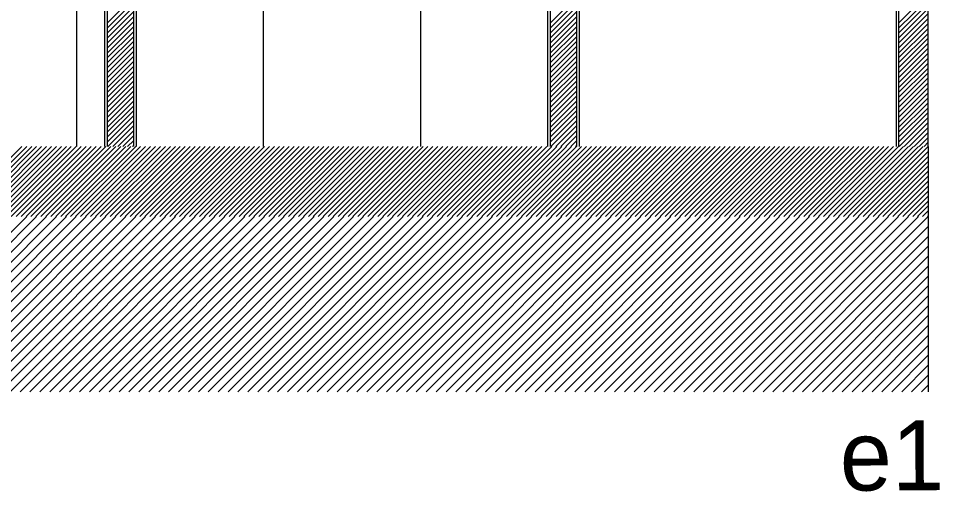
# Model space of a CAD drawing. Extents: x -4333 to -3435, y 16386 to 16556.
# Drawn here: x -3478.31 to -3473.05, y 16401.6 to 16404.3 of the extents above; entities that cross this region are included whole.
import ezdxf

# ---------------------------------------------------------------- set-up
doc = ezdxf.new("R2010")
doc.units = 0
doc.layers.add('Level 2', color=7, linetype='Continuous')
doc.layers.add('Level 63', color=7, linetype='Continuous')

msp = doc.modelspace()

# ---------------------------------------------------------------- linework, layer by layer
at = {"layer": 'Level 2'}
for p, q in [((-3473.1151, 16403.5694), (-3473.1151, 16407.0203)), ((-3477.8183, 16406.6203), (-3477.8184, 16403.5694)), ((-3477.6383, 16406.6203), (-3477.6384, 16403.5694)), ((-3475.2886, 16406.6203), (-3475.2886, 16403.5694)), ((-3475.1085, 16406.6203), (-3475.1086, 16403.5694)), ((-3473.299, 16406.6203), (-3473.299, 16403.5694)), ((-3473.1151, 16403.5694), (-3473.1151, 16402.1694))]:
    msp.add_line(p, q, dxfattribs=at)
at = {"layer": 'Level 63'}
for p, q in [((-3477.9791, 16406.6203), (-3477.9791, 16403.5694)), ((-3477.8033, 16406.6203), (-3477.8034, 16403.5694)), ((-3477.6533, 16406.6203), (-3477.6534, 16403.5694)), ((-3475.2736, 16406.6203), (-3475.2736, 16403.5694)), ((-3475.1235, 16406.6203), (-3475.1236, 16403.5694)), ((-3473.284, 16406.6203), (-3473.284, 16403.5694)), ((-3476.9134, 16405.5694), (-3476.9135, 16403.5694)), ((-3476.0135, 16405.5694), (-3476.0135, 16403.5694)), ((-3477.8034, 16404.2727), (-3477.6534, 16404.4227)), ((-3475.2736, 16404.2727), (-3475.1236, 16404.4227)), ((-3473.284, 16404.2727), (-3473.1151, 16404.4416)), ((-3473.284, 16404.2444), (-3473.1151, 16404.4133)), ((-3477.8034, 16404.2444), (-3477.6534, 16404.3944)), ((-3477.8034, 16404.2161), (-3477.6534, 16404.3661)), ((-3475.2736, 16404.2444), (-3475.1236, 16404.3944)), ((-3475.2736, 16404.2161), (-3475.1236, 16404.3661)), ((-3473.284, 16404.2161), (-3473.1151, 16404.385)), ((-3473.284, 16404.1878), (-3473.1151, 16404.3567)), ((-3477.8034, 16404.1878), (-3477.6534, 16404.3378)), ((-3477.8034, 16404.1596), (-3477.6534, 16404.3096)), ((-3475.2736, 16404.1878), (-3475.1236, 16404.3379)), ((-3475.2736, 16404.1595), (-3475.1236, 16404.3096)), ((-3473.284, 16404.1595), (-3473.1151, 16404.3284)), ((-3473.284, 16404.1313), (-3473.1151, 16404.3002)), ((-3477.8034, 16404.1313), (-3477.6534, 16404.2813)), ((-3477.8034, 16404.103), (-3477.6534, 16404.253)), ((-3475.2736, 16404.1313), (-3475.1236, 16404.2813)), ((-3475.2736, 16404.103), (-3475.1236, 16404.253)), ((-3473.284, 16404.103), (-3473.1151, 16404.2719)), ((-3477.8034, 16404.0747), (-3477.6534, 16404.2247)), ((-3477.8034, 16404.0464), (-3477.6534, 16404.1964)), ((-3475.2736, 16404.0747), (-3475.1236, 16404.2247)), ((-3475.2736, 16404.0464), (-3475.1236, 16404.1964)), ((-3473.284, 16404.0747), (-3473.1151, 16404.2436)), ((-3473.284, 16404.0464), (-3473.1151, 16404.2153)), ((-3477.8034, 16404.0181), (-3477.6534, 16404.1681)), ((-3475.2736, 16404.0181), (-3475.1236, 16404.1682)), ((-3473.284, 16404.0181), (-3473.1151, 16404.187)), ((-3473.284, 16403.9898), (-3473.1151, 16404.1587)), ((-3477.8034, 16403.9899), (-3477.6534, 16404.1399)), ((-3477.8034, 16403.9616), (-3477.6534, 16404.1116)), ((-3475.2736, 16403.9898), (-3475.1236, 16404.1399)), ((-3475.2736, 16403.9616), (-3475.1236, 16404.1116)), ((-3473.284, 16403.9615), (-3473.1151, 16404.1305)), ((-3473.284, 16403.9333), (-3473.1151, 16404.1022)), ((-3477.8034, 16403.9333), (-3477.6534, 16404.0833)), ((-3477.8034, 16403.905), (-3477.6534, 16404.055)), ((-3475.2736, 16403.9333), (-3475.1236, 16404.0833)), ((-3475.2736, 16403.905), (-3475.1236, 16404.055)), ((-3473.284, 16403.905), (-3473.1151, 16404.0739)), ((-3473.284, 16403.8767), (-3473.1151, 16404.0456)), ((-3477.8034, 16403.8767), (-3477.6534, 16404.0267)), ((-3477.8034, 16403.8484), (-3477.6534, 16403.9984)), ((-3475.2736, 16403.8767), (-3475.1236, 16404.0267)), ((-3475.2736, 16403.8484), (-3475.1236, 16403.9984)), ((-3473.284, 16403.8484), (-3473.1151, 16404.0173)), ((-3473.284, 16403.8201), (-3473.1151, 16403.989)), ((-3477.8034, 16403.8202), (-3477.6534, 16403.9701)), ((-3477.8034, 16403.7919), (-3477.6534, 16403.9419)), ((-3475.2736, 16403.8201), (-3475.1236, 16403.9702)), ((-3475.2736, 16403.7918), (-3475.1236, 16403.9419)), ((-3473.284, 16403.7918), (-3473.1151, 16403.9608)), ((-3473.284, 16403.7636), (-3473.1151, 16403.9325)), ((-3477.8034, 16403.7636), (-3477.6534, 16403.9136)), ((-3477.8034, 16403.7353), (-3477.6534, 16403.8853)), ((-3475.2736, 16403.7636), (-3475.1236, 16403.9136)), ((-3475.2736, 16403.7353), (-3475.1236, 16403.8853)), ((-3473.284, 16403.7353), (-3473.1151, 16403.9042)), ((-3477.8034, 16403.707), (-3477.6534, 16403.857)), ((-3477.8034, 16403.6787), (-3477.6534, 16403.8287)), ((-3475.2736, 16403.707), (-3475.1236, 16403.857)), ((-3475.2736, 16403.6787), (-3475.1236, 16403.8287)), ((-3473.284, 16403.707), (-3473.1151, 16403.8759)), ((-3473.284, 16403.6787), (-3473.1151, 16403.8476)), ((-3477.8034, 16403.6504), (-3477.6534, 16403.8004)), ((-3475.2736, 16403.6504), (-3475.1236, 16403.8005)), ((-3473.284, 16403.6504), (-3473.1151, 16403.8193)), ((-3473.284, 16403.6221), (-3473.1151, 16403.791)), ((-3477.8034, 16403.6222), (-3477.6534, 16403.7722)), ((-3477.8034, 16403.5939), (-3477.6534, 16403.7439)), ((-3475.2736, 16403.6221), (-3475.1236, 16403.7722)), ((-3475.2736, 16403.5939), (-3475.1236, 16403.7439)), ((-3473.284, 16403.5938), (-3473.1151, 16403.7628)), ((-3473.2802, 16403.5694), (-3473.1151, 16403.7345)), ((-3477.7995, 16403.5694), (-3477.6534, 16403.7156)), ((-3477.7713, 16403.5694), (-3477.6534, 16403.6873)), ((-3475.2698, 16403.5694), (-3475.1236, 16403.7156)), ((-3475.2415, 16403.5694), (-3475.1236, 16403.6873)), ((-3473.2519, 16403.5694), (-3473.1151, 16403.7062)), ((-3473.2236, 16403.5694), (-3473.1151, 16403.6779)), ((-3477.743, 16403.5694), (-3477.6534, 16403.659)), ((-3477.7147, 16403.5694), (-3477.6534, 16403.6307)), ((-3475.2132, 16403.5694), (-3475.1236, 16403.659)), ((-3475.1849, 16403.5694), (-3475.1236, 16403.6307)), ((-3473.1954, 16403.5694), (-3473.1151, 16403.6496)), ((-3473.1671, 16403.5694), (-3473.1151, 16403.6213)), ((-3478.691, 16403.1694), (-3478.291, 16403.5694)), ((-3478.6627, 16403.1694), (-3478.2627, 16403.5694)), ((-3478.6344, 16403.1694), (-3478.2344, 16403.5694)), ((-3478.6061, 16403.1694), (-3478.2061, 16403.5694)), ((-3478.5778, 16403.1694), (-3478.1778, 16403.5694)), ((-3478.5495, 16403.1694), (-3478.1495, 16403.5694)), ((-3478.5212, 16403.1694), (-3478.1213, 16403.5694)), ((-3478.493, 16403.1694), (-3478.093, 16403.5694)), ((-3478.4647, 16403.1694), (-3478.0647, 16403.5694)), ((-3478.4364, 16403.1694), (-3478.0364, 16403.5694)), ((-3478.4081, 16403.1694), (-3478.0081, 16403.5694)), ((-3478.3798, 16403.1694), (-3477.9798, 16403.5694)), ((-3478.3515, 16403.1694), (-3477.9515, 16403.5694)), ((-3478.3233, 16403.1694), (-3477.9233, 16403.5694)), ((-3478.295, 16403.1694), (-3477.895, 16403.5694)), ((-3478.2667, 16403.1694), (-3477.8667, 16403.5694)), ((-3478.2384, 16403.1694), (-3477.8384, 16403.5694)), ((-3478.2101, 16403.1694), (-3477.8101, 16403.5694)), ((-3478.1818, 16403.1694), (-3477.7818, 16403.5694)), ((-3478.1536, 16403.1694), (-3477.7536, 16403.5694)), ((-3478.1253, 16403.1694), (-3477.7253, 16403.5694)), ((-3478.097, 16403.1694), (-3477.697, 16403.5694)), ((-3478.0687, 16403.1694), (-3477.6687, 16403.5694)), ((-3478.0404, 16403.1694), (-3477.6404, 16403.5694)), ((-3478.0121, 16403.1694), (-3477.6121, 16403.5694)), ((-3477.9838, 16403.1694), (-3477.5838, 16403.5694)), ((-3477.9556, 16403.1694), (-3477.5556, 16403.5694)), ((-3477.9273, 16403.1694), (-3477.5273, 16403.5694)), ((-3477.899, 16403.1694), (-3477.499, 16403.5694)), ((-3477.8707, 16403.1694), (-3477.4707, 16403.5694)), ((-3477.8424, 16403.1694), (-3477.4424, 16403.5694)), ((-3477.8141, 16403.1694), (-3477.4141, 16403.5694)), ((-3477.7859, 16403.1694), (-3477.3859, 16403.5694)), ((-3477.7576, 16403.1694), (-3477.3576, 16403.5694)), ((-3477.7293, 16403.1694), (-3477.3293, 16403.5694)), ((-3477.701, 16403.1694), (-3477.301, 16403.5694)), ((-3477.6864, 16403.5694), (-3477.6534, 16403.6025)), ((-3477.6727, 16403.1694), (-3477.2727, 16403.5694)), ((-3477.6581, 16403.5694), (-3477.6534, 16403.5742)), ((-3477.6444, 16403.1694), (-3477.2444, 16403.5694)), ((-3477.6162, 16403.1694), (-3477.2161, 16403.5694)), ((-3477.5879, 16403.1694), (-3477.1879, 16403.5694)), ((-3477.5596, 16403.1694), (-3477.1596, 16403.5694)), ((-3477.5313, 16403.1694), (-3477.1313, 16403.5694)), ((-3477.503, 16403.1694), (-3477.103, 16403.5694)), ((-3477.4747, 16403.1694), (-3477.0747, 16403.5694)), ((-3477.4464, 16403.1694), (-3477.0464, 16403.5694)), ((-3477.4182, 16403.1694), (-3477.0182, 16403.5694)), ((-3477.3899, 16403.1694), (-3476.9899, 16403.5694)), ((-3477.3616, 16403.1694), (-3476.9616, 16403.5694)), ((-3477.3333, 16403.1694), (-3476.9333, 16403.5694)), ((-3477.305, 16403.1694), (-3476.905, 16403.5694)), ((-3477.2767, 16403.1694), (-3476.8767, 16403.5694)), ((-3477.2485, 16403.1694), (-3476.8485, 16403.5694)), ((-3477.2202, 16403.1694), (-3476.8202, 16403.5694)), ((-3477.1919, 16403.1694), (-3476.7919, 16403.5694)), ((-3477.1636, 16403.1694), (-3476.7636, 16403.5694)), ((-3477.1353, 16403.1694), (-3476.7353, 16403.5694)), ((-3477.107, 16403.1694), (-3476.707, 16403.5694)), ((-3477.0788, 16403.1694), (-3476.6788, 16403.5694)), ((-3477.0505, 16403.1694), (-3476.6505, 16403.5694)), ((-3477.0222, 16403.1694), (-3476.6222, 16403.5694)), ((-3476.9939, 16403.1694), (-3476.5939, 16403.5694)), ((-3476.9656, 16403.1694), (-3476.5656, 16403.5694)), ((-3476.9373, 16403.1694), (-3476.5373, 16403.5694)), ((-3476.9091, 16403.1694), (-3476.5091, 16403.5694)), ((-3476.8808, 16403.1694), (-3476.4808, 16403.5694)), ((-3476.8525, 16403.1694), (-3476.4525, 16403.5694)), ((-3476.8242, 16403.1694), (-3476.4242, 16403.5694)), ((-3476.7959, 16403.1694), (-3476.3959, 16403.5694)), ((-3476.7676, 16403.1694), (-3476.3676, 16403.5694)), ((-3476.7393, 16403.1694), (-3476.3393, 16403.5694)), ((-3476.7111, 16403.1694), (-3476.3111, 16403.5694)), ((-3476.6828, 16403.1694), (-3476.2828, 16403.5694)), ((-3476.6545, 16403.1694), (-3476.2545, 16403.5694)), ((-3476.6262, 16403.1694), (-3476.2262, 16403.5694)), ((-3476.5979, 16403.1694), (-3476.1979, 16403.5694)), ((-3476.5696, 16403.1694), (-3476.1696, 16403.5694)), ((-3476.5414, 16403.1694), (-3476.1414, 16403.5694)), ((-3476.5131, 16403.1694), (-3476.1131, 16403.5694)), ((-3476.4848, 16403.1694), (-3476.0848, 16403.5694)), ((-3476.4565, 16403.1694), (-3476.0565, 16403.5694)), ((-3476.4282, 16403.1694), (-3476.0282, 16403.5694)), ((-3476.3999, 16403.1694), (-3475.9999, 16403.5694)), ((-3476.3716, 16403.1694), (-3475.9716, 16403.5694)), ((-3476.3434, 16403.1694), (-3475.9434, 16403.5694)), ((-3476.3151, 16403.1694), (-3475.9151, 16403.5694)), ((-3476.2868, 16403.1694), (-3475.8868, 16403.5694)), ((-3476.2585, 16403.1694), (-3475.8585, 16403.5694)), ((-3476.2302, 16403.1694), (-3475.8302, 16403.5694)), ((-3476.2019, 16403.1694), (-3475.8019, 16403.5694)), ((-3476.1737, 16403.1694), (-3475.7737, 16403.5694)), ((-3476.1454, 16403.1694), (-3475.7454, 16403.5694)), ((-3476.1171, 16403.1694), (-3475.7171, 16403.5694)), ((-3476.0888, 16403.1694), (-3475.6888, 16403.5694)), ((-3476.0605, 16403.1694), (-3475.6605, 16403.5694)), ((-3476.0322, 16403.1694), (-3475.6322, 16403.5694)), ((-3476.0039, 16403.1694), (-3475.6039, 16403.5694)), ((-3475.9757, 16403.1694), (-3475.5757, 16403.5694)), ((-3475.9474, 16403.1694), (-3475.5474, 16403.5694)), ((-3475.9191, 16403.1694), (-3475.5191, 16403.5694)), ((-3475.8908, 16403.1694), (-3475.4908, 16403.5694)), ((-3475.8625, 16403.1694), (-3475.4625, 16403.5694)), ((-3475.8342, 16403.1694), (-3475.4342, 16403.5694)), ((-3475.806, 16403.1694), (-3475.406, 16403.5694)), ((-3475.7777, 16403.1694), (-3475.3777, 16403.5694)), ((-3475.7494, 16403.1694), (-3475.3494, 16403.5694)), ((-3475.7211, 16403.1694), (-3475.3211, 16403.5694)), ((-3475.6928, 16403.1694), (-3475.2928, 16403.5694)), ((-3475.6645, 16403.1694), (-3475.2645, 16403.5694)), ((-3475.6363, 16403.1694), (-3475.2363, 16403.5694)), ((-3475.608, 16403.1694), (-3475.208, 16403.5694)), ((-3475.5797, 16403.1694), (-3475.1797, 16403.5694)), ((-3475.5514, 16403.1694), (-3475.1514, 16403.5694)), ((-3475.5231, 16403.1694), (-3475.1231, 16403.5694)), ((-3475.4948, 16403.1694), (-3475.0948, 16403.5694)), ((-3475.4665, 16403.1694), (-3475.0666, 16403.5694)), ((-3475.4383, 16403.1694), (-3475.0383, 16403.5694)), ((-3475.41, 16403.1694), (-3475.01, 16403.5694)), ((-3475.3817, 16403.1694), (-3474.9817, 16403.5694)), ((-3475.3534, 16403.1694), (-3474.9534, 16403.5694)), ((-3475.3251, 16403.1694), (-3474.9251, 16403.5694)), ((-3475.2968, 16403.1694), (-3474.8968, 16403.5694)), ((-3475.2686, 16403.1694), (-3474.8686, 16403.5694)), ((-3475.2403, 16403.1694), (-3474.8403, 16403.5694)), ((-3475.212, 16403.1694), (-3474.812, 16403.5694)), ((-3475.1837, 16403.1694), (-3474.7837, 16403.5694)), ((-3475.1566, 16403.5694), (-3475.1236, 16403.6025)), ((-3475.1554, 16403.1694), (-3474.7554, 16403.5694)), ((-3475.1284, 16403.5694), (-3475.1236, 16403.5742)), ((-3475.1271, 16403.1694), (-3474.7271, 16403.5694)), ((-3475.0989, 16403.1694), (-3474.6989, 16403.5694)), ((-3475.0706, 16403.1694), (-3474.6706, 16403.5694)), ((-3475.0423, 16403.1694), (-3474.6423, 16403.5694)), ((-3475.014, 16403.1694), (-3474.614, 16403.5694)), ((-3474.9857, 16403.1694), (-3474.5857, 16403.5694)), ((-3474.9574, 16403.1694), (-3474.5574, 16403.5694)), ((-3474.9291, 16403.1694), (-3474.5291, 16403.5694)), ((-3474.9009, 16403.1694), (-3474.5009, 16403.5694)), ((-3474.8726, 16403.1694), (-3474.4726, 16403.5694)), ((-3474.8443, 16403.1694), (-3474.4443, 16403.5694)), ((-3474.816, 16403.1694), (-3474.416, 16403.5694)), ((-3474.7877, 16403.1694), (-3474.3877, 16403.5694)), ((-3474.7594, 16403.1694), (-3474.3594, 16403.5694)), ((-3474.7312, 16403.1694), (-3474.3312, 16403.5694)), ((-3474.7029, 16403.1694), (-3474.3029, 16403.5694)), ((-3474.6746, 16403.1694), (-3474.2746, 16403.5694)), ((-3474.6463, 16403.1694), (-3474.2463, 16403.5694)), ((-3474.618, 16403.1694), (-3474.218, 16403.5694)), ((-3474.5897, 16403.1694), (-3474.1897, 16403.5694)), ((-3474.5615, 16403.1694), (-3474.1614, 16403.5694)), ((-3474.5332, 16403.1694), (-3474.1332, 16403.5694)), ((-3474.5049, 16403.1694), (-3474.1049, 16403.5694)), ((-3474.4766, 16403.1694), (-3474.0766, 16403.5694)), ((-3474.4483, 16403.1694), (-3474.0483, 16403.5694)), ((-3474.42, 16403.1694), (-3474.02, 16403.5694)), ((-3474.3917, 16403.1694), (-3473.9917, 16403.5694)), ((-3474.3635, 16403.1694), (-3473.9635, 16403.5694)), ((-3474.3352, 16403.1694), (-3473.9352, 16403.5694)), ((-3474.3069, 16403.1694), (-3473.9069, 16403.5694)), ((-3474.2786, 16403.1694), (-3473.8786, 16403.5694)), ((-3474.2503, 16403.1694), (-3473.8503, 16403.5694)), ((-3474.222, 16403.1694), (-3473.822, 16403.5694)), ((-3474.1938, 16403.1694), (-3473.7938, 16403.5694)), ((-3474.1655, 16403.1694), (-3473.7655, 16403.5694)), ((-3474.1372, 16403.1694), (-3473.7372, 16403.5694)), ((-3474.1089, 16403.1694), (-3473.7089, 16403.5694)), ((-3474.0806, 16403.1694), (-3473.6806, 16403.5694)), ((-3474.0523, 16403.1694), (-3473.6523, 16403.5694)), ((-3474.024, 16403.1694), (-3473.6241, 16403.5694)), ((-3473.9958, 16403.1694), (-3473.5958, 16403.5694)), ((-3473.9675, 16403.1694), (-3473.5675, 16403.5694)), ((-3473.9392, 16403.1694), (-3473.5392, 16403.5694)), ((-3473.9109, 16403.1694), (-3473.5109, 16403.5694)), ((-3473.8826, 16403.1694), (-3473.4826, 16403.5694)), ((-3473.8543, 16403.1694), (-3473.4543, 16403.5694)), ((-3473.8261, 16403.1694), (-3473.4261, 16403.5694)), ((-3473.7978, 16403.1694), (-3473.3978, 16403.5694)), ((-3473.7695, 16403.1694), (-3473.3695, 16403.5694)), ((-3473.7412, 16403.1694), (-3473.3412, 16403.5694)), ((-3473.7129, 16403.1694), (-3473.3129, 16403.5694)), ((-3473.6846, 16403.1694), (-3473.2846, 16403.5694)), ((-3473.6564, 16403.1694), (-3473.2564, 16403.5694)), ((-3473.6281, 16403.1694), (-3473.2281, 16403.5694)), ((-3473.5998, 16403.1694), (-3473.1998, 16403.5694)), ((-3473.5715, 16403.1694), (-3473.1715, 16403.5694)), ((-3473.5432, 16403.1694), (-3473.1432, 16403.5694)), ((-3473.5149, 16403.1694), (-3473.1151, 16403.5692)), ((-3473.1388, 16403.5694), (-3473.1151, 16403.5931)), ((-3473.4866, 16403.1694), (-3473.1151, 16403.5409)), ((-3473.4584, 16403.1694), (-3473.1151, 16403.5126)), ((-3473.4301, 16403.1694), (-3473.1151, 16403.4844)), ((-3473.4018, 16403.1694), (-3473.1151, 16403.4561)), ((-3473.3735, 16403.1694), (-3473.1151, 16403.4278)), ((-3473.3452, 16403.1694), (-3473.1151, 16403.3995)), ((-3473.3169, 16403.1694), (-3473.1151, 16403.3712)), ((-3473.2887, 16403.1694), (-3473.1151, 16403.3429)), ((-3473.2604, 16403.1694), (-3473.1151, 16403.3147)), ((-3473.2321, 16403.1694), (-3473.1151, 16403.2864)), ((-3473.2038, 16403.1694), (-3473.1151, 16403.2581)), ((-3473.1755, 16403.1694), (-3473.1151, 16403.2298)), ((-3473.1472, 16403.1694), (-3473.1151, 16403.2015)), ((-3479.2627, 16402.1694), (-3478.2627, 16403.1694)), ((-3479.2061, 16402.1694), (-3478.2061, 16403.1694)), ((-3479.1495, 16402.1694), (-3478.1495, 16403.1694)), ((-3479.093, 16402.1694), (-3478.093, 16403.1694)), ((-3479.0364, 16402.1694), (-3478.0364, 16403.1694)), ((-3478.9798, 16402.1694), (-3477.9798, 16403.1694)), ((-3478.9233, 16402.1694), (-3477.9233, 16403.1694)), ((-3478.8667, 16402.1694), (-3477.8667, 16403.1694)), ((-3478.8101, 16402.1694), (-3477.8101, 16403.1694)), ((-3478.7536, 16402.1694), (-3477.7536, 16403.1694)), ((-3478.697, 16402.1694), (-3477.697, 16403.1694)), ((-3478.6404, 16402.1694), (-3477.6404, 16403.1694)), ((-3478.5839, 16402.1694), (-3477.5838, 16403.1694)), ((-3478.5273, 16402.1694), (-3477.5273, 16403.1694)), ((-3478.4707, 16402.1694), (-3477.4707, 16403.1694)), ((-3478.4142, 16402.1694), (-3477.4141, 16403.1694)), ((-3478.3576, 16402.1694), (-3477.3576, 16403.1694)), ((-3478.301, 16402.1694), (-3477.301, 16403.1694)), ((-3478.2445, 16402.1694), (-3477.2444, 16403.1694)), ((-3478.1879, 16402.1694), (-3477.1879, 16403.1694)), ((-3478.1313, 16402.1694), (-3477.1313, 16403.1694)), ((-3478.0747, 16402.1694), (-3477.0747, 16403.1694)), ((-3478.0182, 16402.1694), (-3477.0182, 16403.1694)), ((-3477.9616, 16402.1694), (-3476.9616, 16403.1694)), ((-3477.905, 16402.1694), (-3476.905, 16403.1694)), ((-3477.8485, 16402.1694), (-3476.8485, 16403.1694)), ((-3477.7919, 16402.1694), (-3476.7919, 16403.1694)), ((-3477.7353, 16402.1694), (-3476.7353, 16403.1694)), ((-3477.6788, 16402.1694), (-3476.6788, 16403.1694)), ((-3477.6222, 16402.1694), (-3476.6222, 16403.1694)), ((-3477.5656, 16402.1694), (-3476.5656, 16403.1694)), ((-3477.5091, 16402.1694), (-3476.5091, 16403.1694)), ((-3477.4525, 16402.1694), (-3476.4525, 16403.1694)), ((-3477.3959, 16402.1694), (-3476.3959, 16403.1694)), ((-3477.3393, 16402.1694), (-3476.3393, 16403.1694)), ((-3477.2828, 16402.1694), (-3476.2828, 16403.1694)), ((-3477.2262, 16402.1694), (-3476.2262, 16403.1694)), ((-3477.1696, 16402.1694), (-3476.1696, 16403.1694)), ((-3477.1131, 16402.1694), (-3476.1131, 16403.1694)), ((-3477.0565, 16402.1694), (-3476.0565, 16403.1694)), ((-3476.9999, 16402.1694), (-3475.9999, 16403.1694)), ((-3476.9434, 16402.1694), (-3475.9434, 16403.1694)), ((-3476.8868, 16402.1694), (-3475.8868, 16403.1694)), ((-3476.8302, 16402.1694), (-3475.8302, 16403.1694)), ((-3476.7737, 16402.1694), (-3475.7737, 16403.1694)), ((-3476.7171, 16402.1694), (-3475.7171, 16403.1694)), ((-3476.6605, 16402.1694), (-3475.6605, 16403.1694)), ((-3476.604, 16402.1694), (-3475.604, 16403.1694)), ((-3476.5474, 16402.1694), (-3475.5474, 16403.1694)), ((-3476.4908, 16402.1694), (-3475.4908, 16403.1694)), ((-3476.4343, 16402.1694), (-3475.4342, 16403.1694)), ((-3476.3777, 16402.1694), (-3475.3777, 16403.1694)), ((-3476.3211, 16402.1694), (-3475.3211, 16403.1694)), ((-3476.2645, 16402.1694), (-3475.2645, 16403.1694)), ((-3476.208, 16402.1694), (-3475.208, 16403.1694)), ((-3476.1514, 16402.1694), (-3475.1514, 16403.1694)), ((-3476.0948, 16402.1694), (-3475.0948, 16403.1694)), ((-3476.0383, 16402.1694), (-3475.0383, 16403.1694)), ((-3475.9817, 16402.1694), (-3474.9817, 16403.1694)), ((-3475.9251, 16402.1694), (-3474.9251, 16403.1694)), ((-3475.8686, 16402.1694), (-3474.8686, 16403.1694)), ((-3475.812, 16402.1694), (-3474.812, 16403.1694)), ((-3475.7554, 16402.1694), (-3474.7554, 16403.1694)), ((-3475.6989, 16402.1694), (-3474.6989, 16403.1694)), ((-3475.6423, 16402.1694), (-3474.6423, 16403.1694)), ((-3475.5857, 16402.1694), (-3474.5857, 16403.1694)), ((-3475.5292, 16402.1694), (-3474.5291, 16403.1694)), ((-3475.4726, 16402.1694), (-3474.4726, 16403.1694)), ((-3475.416, 16402.1694), (-3474.416, 16403.1694)), ((-3475.3595, 16402.1694), (-3474.3594, 16403.1694)), ((-3475.3029, 16402.1694), (-3474.3029, 16403.1694)), ((-3475.2463, 16402.1694), (-3474.2463, 16403.1694)), ((-3475.1898, 16402.1694), (-3474.1897, 16403.1694)), ((-3475.1332, 16402.1694), (-3474.1332, 16403.1694)), ((-3475.0766, 16402.1694), (-3474.0766, 16403.1694)), ((-3475.02, 16402.1694), (-3474.02, 16403.1694)), ((-3474.9635, 16402.1694), (-3473.9635, 16403.1694)), ((-3474.9069, 16402.1694), (-3473.9069, 16403.1694)), ((-3474.8503, 16402.1694), (-3473.8503, 16403.1694)), ((-3474.7938, 16402.1694), (-3473.7938, 16403.1694)), ((-3474.7372, 16402.1694), (-3473.7372, 16403.1694)), ((-3474.6806, 16402.1694), (-3473.6806, 16403.1694)), ((-3474.6241, 16402.1694), (-3473.6241, 16403.1694)), ((-3474.5675, 16402.1694), (-3473.5675, 16403.1694)), ((-3474.5109, 16402.1694), (-3473.5109, 16403.1694)), ((-3474.4544, 16402.1694), (-3473.4543, 16403.1694)), ((-3474.3978, 16402.1694), (-3473.3978, 16403.1694)), ((-3474.3412, 16402.1694), (-3473.3412, 16403.1694)), ((-3474.2846, 16402.1694), (-3473.2846, 16403.1694)), ((-3474.2281, 16402.1694), (-3473.2281, 16403.1694)), ((-3474.1715, 16402.1694), (-3473.1715, 16403.1694)), ((-3474.1149, 16402.1694), (-3473.1151, 16403.1692)), ((-3473.119, 16403.1694), (-3473.1151, 16403.1732)), ((-3474.0584, 16402.1694), (-3473.1151, 16403.1127)), ((-3474.0018, 16402.1694), (-3473.1151, 16403.0561)), ((-3473.9452, 16402.1694), (-3473.1151, 16402.9995)), ((-3473.8887, 16402.1694), (-3473.1151, 16402.9429)), ((-3473.8321, 16402.1694), (-3473.1151, 16402.8864)), ((-3473.7755, 16402.1694), (-3473.1151, 16402.8298)), ((-3473.719, 16402.1694), (-3473.1151, 16402.7732)), ((-3473.6624, 16402.1694), (-3473.1151, 16402.7167)), ((-3473.6058, 16402.1694), (-3473.1151, 16402.6601)), ((-3473.5493, 16402.1694), (-3473.1151, 16402.6035)), ((-3473.4927, 16402.1694), (-3473.1151, 16402.547)), ((-3473.4361, 16402.1694), (-3473.1151, 16402.4904)), ((-3473.3796, 16402.1694), (-3473.1151, 16402.4338)), ((-3473.323, 16402.1694), (-3473.1151, 16402.3773)), ((-3473.2664, 16402.1694), (-3473.1151, 16402.3207)), ((-3473.2098, 16402.1694), (-3473.1151, 16402.2641)), ((-3473.1533, 16402.1694), (-3473.1151, 16402.2075))]:
    msp.add_line(p, q, dxfattribs=at)

# ---------------------------------------------------------------- texts
at = {"layer": 'Level 2'}
msp.add_text('e1', height=0.4, rotation=0.2978, dxfattribs=at).set_placement((-3473.6191, 16401.6042))

doc.saveas('drawing.dxf')
